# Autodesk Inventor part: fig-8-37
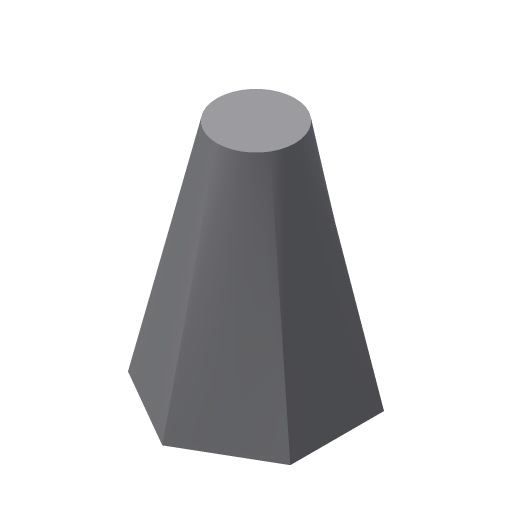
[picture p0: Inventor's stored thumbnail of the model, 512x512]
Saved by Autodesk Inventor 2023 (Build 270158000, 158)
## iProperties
Created: 2007-05
Part Number: fig-8-37
Document SubType Name: Modeling
Designer: Administrator
Density: 1 g/cm^3
Material: Generic
Appearance: Default
Author: Administrator
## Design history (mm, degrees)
sketch "Sketch1"
  geometry: L1 (0, 30)-(25.981, 15); L2 (25.981, 15)-(25.981, -15); L3 (25.981, -15)-(0, -30); L4 (0, -30)-(-25.981, -15); L5 (-25.981, -15)-(-25.981, 15); L6 (-25.981, 15)-(0, 30); 2 further points
  constraints: 12 end point, 1 coincident, 1 vertical, 14 other
workplane "Work Plane1"
sketch "Sketch2"
  geometry: C1 r 12.5 at (0, 0)
  constraints: 1 centre point, 1 other
sketch "Sketch3"
  geometry: L1 (0, 0)-(0, 75)
  constraints: 2 end point, 1 vertical, 1 other
loft "Loft1" dims "d5" = 0, "d6" = 90 deg, "d7" = 0, "d8" = 90 deg
body "Solid1"
other parameters: "d1" = 75
